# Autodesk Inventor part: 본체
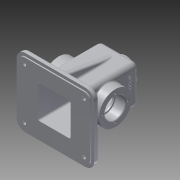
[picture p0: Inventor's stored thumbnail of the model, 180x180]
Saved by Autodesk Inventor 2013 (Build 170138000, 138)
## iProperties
Created: 2016-01
Part Number: 본체
Material: 알루미늄 6061
Document SubType Name: Modeling
Designer: User
Density: 2.71 g/cm^3
Mass: 806.269 g
Surface Area: 909.624 cm^2
Volume: 297.516 cm^3
Author: User
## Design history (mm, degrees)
sketch "스케치1"
  geometry: L1 (-32.5, 50)-(32.5, 50); L2 (32.5, 50)-(32.5, -50); L3 (32.5, -50)-(-32.5, -50); L4 (-32.5, -50)-(-32.5, 50); 3 further points
  constraints: 8 end point, 2 midpoint, 2 parallel, 1 horizontal, 1 horizontal alignment, 1 perpendicular, 1 vertical alignment
  dimensions: "d6" = 65 distance between parallel lines of L2 L4; "d8" = 100 distance between parallel lines of L3 L1
extrude "돌출1" new body sketch "스케치1" distance "d9" = 65; taper "d10" = 0 deg
sketch "스케치2"
  geometry: L1 (65, 0)-(65, 65) reference; L2 (0, 65)-(65, 65) reference; L3 (-32.5, 90)-(97.5, 90); L4 (97.5, 90)-(97.5, -25); L5 (97.5, -25)-(-32.5, -25); L6 (-32.5, -25)-(-32.5, 90); 5 further points
  constraints: 8 end point, 4 midpoint, 2 parallel, 1 horizontal, 1 horizontal alignment, 1 perpendicular, 1 vertical alignment
  dimensions: "d11" = 115 distance of L3.end L4.end; "d13" = 130 distance of L3.start L3.end
extrude "돌출2" join sketch "스케치2" distance "d14" = 10; taper "d15" = 0 deg
sketch "스케치3"
  geometry: L1 (97.5, 90)-(-32.5, 90) reference; L2 (97.5, -25)-(97.5, 90) reference; L3 (5, 60)-(60, 60); L4 (60, 60)-(60, 5); L5 (60, 5)-(5, 5); L6 (5, 5)-(5, 60); 5 further points
  constraints: 8 end point, 4 midpoint, 2 parallel, 1 horizontal, 1 horizontal alignment, 1 perpendicular, 1 vertical alignment
  dimensions: "d16" = 55 distance of L3.start L3.end; "d18" = 55 distance of L3.end L4.end
extrude "돌출3" cut sketch "스케치3" distance "d19" = 105; taper "d20" = 0 deg
sketch "스케치4"
  geometry: L1 (0, 0)-(65, 0) reference; L2 (90, -110)-(-25, -110) reference; C1 r 27.5 at (32.5, -55); 2 further points
  constraints: 1 centre point, 1 midpoint, 1 vertical alignment
  dimensions: "d21" = 55 diameter of C1; "d22" = 55 distance from line of C1.centre L2
extrude "돌출4" join sketch "스케치4" distance "d23" = 15; taper "d24" = 0 deg
sketch "스케치5"
  geometry: L1 (65, 0)-(0, 0) reference; L2 (90, -110)-(-25, -110) reference; C1 r 27.5 at (32.5, -55); 2 further points
  constraints: 1 centre point, 1 midpoint, 1 vertical alignment
  dimensions: "d25" = 55 diameter of C1; "d26" = 55 distance from line of C1.centre L2
extrude "돌출5" join sketch "스케치5" distance "d27" = 15; taper "d28" = 0 deg
sketch "스케치6"
  geometry: C1 r 27.5 at (0, 0) reference; C2 r 17.5 at (0, 0); C3 r 15 at (0, 0); 1 further point
  constraints: 2 centre point, 2 coincident
  dimensions: "d29" = 35 diameter of C2; "d30" = 30 diameter of C3
extrude "돌출6" cut sketch "스케치6" stored distance "d31" = 17; taper "d32" = 0 deg
extrude "돌출7" cut sketch "스케치6" distance "d33" = 17; taper "d34" = 0 deg
sketch "스케치7"
  geometry: C1 r 15 at (0, 0) reference; C2 r 27.5 at (0, 0) reference; C3 r 17.5 at (0, 0); 1 further point
  constraints: 1 centre point, 1 coincident
  dimensions: "d35" = 35 diameter of C3
extrude "돌출8" cut sketch "스케치7" distance "d36" = 17; taper "d37" = 0 deg
sketch "스케치8"
  geometry: L1 (0, 0)-(65, 0) reference; L2 (65, 0)-(65, -65) reference; C1 r 20 at (32.5, -32.5); 3 further points
  constraints: 2 midpoint, 1 centre point, 1 horizontal alignment, 1 vertical alignment
  dimensions: "d38" = 40 diameter of C1
extrude "돌출9" join sketch "스케치8" distance "d39" = 10; taper "d40" = 0 deg
sketch "스케치9"
  geometry: C1 r 20 at (0, 0) reference; C2 r 10.5 at (0, 0); 1 further point
  constraints: 1 centre point, 1 coincident
  dimensions: "d41" = 21 diameter of C2
extrude "돌출10" cut sketch "스케치9" distance "d42" = 46.75; taper "d43" = 0 deg
fillet "모깎기1" dims "d44" = 15
sketch "스케치10"
  geometry: C1 r 7.5 at (-17.5, 10); C2 r 7.5 at (82.5, 10); C3 r 7.5 at (82.5, -75); C4 r 7.5 at (-17.5, -75); C5 r 3 at (-17.5, 10); C6 r 3 at (82.5, 10); C7 r 3 at (82.5, -75); C8 r 3 at (-17.5, -75); A1 r 15 centre (-17.5, 10) between (-17.5, 25) and (-32.5, 10) reference; A2 r 15 centre (-17.5, -75) between (-32.5, -75) and (-17.5, -90) reference; A3 r 15 centre (82.5, -75) between (82.5, -90) and (97.5, -75) reference; A4 r 15 centre (82.5, 10) between (97.5, 10) and (82.5, 25) reference; 1 further point
  constraints: 8 centre point, 8 coincident
  dimensions: "d45" = 15 diameter of C1; "d46" = 15 diameter of C2; "d47" = 15 diameter of C3; "d48" = 15 diameter of C4; "d56" = 6 diameter of C5; "d57" = 6 diameter of C6; "d58" = 6 diameter of C7; "d59" = 6 diameter of C8
extrude "돌출11" cut sketch "스케치10" stored distance "d60" = 15 (= d47); taper "d61" = 0 deg
extrude "돌출12" join sketch "스케치10" distance "d62" = 3; taper "d63" = 0 deg
sketch "스케치11"
  geometry: L1 (-17.5, -25)-(82.5, -25) reference; L2 (97.5, -10)-(97.5, 75) reference; L3 (82.5, 90)-(-17.5, 90) reference; L4 (-32.5, 75)-(-32.5, -10) reference; L5 (-27.5, 85)-(92.5, 85); L6 (92.5, 85)-(92.5, -20); L7 (-27.5, -20)-(-27.5, 85); L8 (5, 5)-(5, 60) reference; L9 (5, 60)-(60, 60) reference; L10 (60, 5)-(5, 5) reference; L11 (92.5, -20)-(-27.5, -20); A1 r 15 centre (-17.5, -10) between (-32.5, -10) and (-17.5, -25) reference; A2 r 15 centre (82.5, -10) between (82.5, -25) and (97.5, -10) reference; A3 r 15 centre (82.5, 75) between (97.5, 75) and (82.5, 90) reference; A4 r 15 centre (-17.5, 75) between (-17.5, 90) and (-32.5, 75) reference; 7 further points
  constraints: 8 end point, 6 midpoint, 2 parallel, 2 vertical alignment, 1 horizontal alignment
  dimensions: "d64" = 5 distance between parallel lines of L2 L6; "d115" = 105 distance between parallel lines of L11 L5
extrude "돌출13" cut sketch "스케치11" distance "d65" = 2; taper "d66" = 0 deg
node "작업 평면2"
sketch "스케치12"
  geometry: L1 (-25, -100)-(-10, -100) reference; L2 (-17.5, -100)-(-2.5, -100) reference; L3 (75, -100)-(-10, -100) reference; L4 (0, 0)-(0, -100) reference; L5 (75, -100)-(90, -100) reference; L6 (65, -100)-(65, 0) reference; L7 (-15, -100)-(0, -14.931); L8 (80, -100)-(65, -14.931); 1 further point
  constraints: 4 end point, 4 point on line
  dimensions: "d67" = 10 distance of L7.start L1.start; "d68" = 10 distance of L8.start L5.end; "d71" = 10 deg angle of L6 L8; "d72" = 10 deg angle of L4 L7
feature "리브1" dims "d73" = 1, "d74" = 10, "d75" = 0, "d76" = 0, "d77" = 1, "d78" = 1
feature "리브2" dims "d79" = 1, "d80" = 10, "d81" = 0, "d82" = 0, "d83" = 1, "d84" = 1
sketch "스케치13" dims "d85" = 42
  geometry: C1 r 27.5 at (0, 0) reference; 3 further points
  constraints: 2 vertical alignment, 1 coincident, 2 other
hole "구멍2" sketch "스케치13" at (0, 21) diameter "d86" = 3.242; stored, may be unused: countersink angle "d90" = 90 deg, drill point angle "d92" = 118 deg; dims "d87" = 8, "d88" = 4, "d89" = 2, "d91" = 10
sketch "스케치14" dims "d96" = 29
  geometry: C1 r 10.5 at (0, 0) reference; 3 further points
  constraints: 2 vertical alignment, 1 coincident, 2 other
hole "구멍3" sketch "스케치14" at (0, 14.5) diameter "d97" = 2.459; stored, may be unused: countersink angle "d101" = 90 deg, drill point angle "d103" = 118 deg; dims "d98" = 7, "d99" = 4, "d100" = 2, "d102" = 9
fillet "모깎기2" dims "d107" = 0.3
fillet "모깎기3" dims "d108" = 0.3
chamfer "모따기1" distance "d109" = 1; stored, may be unused: second distance "d110" = 2, angle "d111" = 45 deg
chamfer "모따기2" distance "d112" = 1; stored, may be unused: second distance "d113" = 2, angle "d114" = 45 deg
fillet "모깎기4" dims "d116" = 10
node "작업 평면3"
sketch "스케치15"
  geometry: L1 (50, -50)-(-50, -50) reference; L2 (-32.5, -50)-(-32.5, 50) reference; L3 (-32.5, -32.5)-(-47.5, -32.5) reference; L4 (32.5, 50)-(32.5, -50) reference; L5 (32.5, -32.5)-(47.5, -32.5) reference; L6 (42.5, -32.5)-(42.5, -50); L7 (-42.5, -32.5)-(-42.5, -50); L8 (-27.5, -60)-(-27.5, 45) reference; L9 (27.5, -60)-(27.5, 45) reference; 1 further point
  constraints: 4 end point, 4 point on line, 1 parallel, 1 vertical
  dimensions: "d117" = 15 distance between parallel lines of L7 L8; "d118" = 15 distance between parallel lines of L6 L9
feature "리브3" dims "d119" = 1, "d120" = 6, "d121" = 0, "d122" = 0, "d123" = 1, "d124" = 1
feature "리브4" dims "d125" = 1, "d126" = 6, "d127" = 0, "d128" = 0, "d129" = 1, "d130" = 1
fillet "모깎기5" dims "d131" = 8
fillet "모깎기6" dims "d132" = 8
fillet "모깎기7" dims "d133" = 3
fillet "모깎기8" dims "d134" = 3
fillet "모깎기9" dims "d135" = 1
fillet "모깎기10" dims "d136" = 3
fillet "모깎기12" dims "d138" = 3
sketch "스케치16"
  geometry: L1 (-8, 0)-(-8, -91) reference; L2 (44.5, 18)-(4.5, 18) reference; 2 further points
  constraints: 1 other
  dimensions: "d139" = 32.5 distance from line of point (24.5, -8) L1; "d140" = 26 distance from line of point (24.5, -8) L2
feature "엠보싱1" sketch "스케치16" dims "d141" = 0.5, "d142" = 0
feature "면 기울기1" dims angle "d143" = 5 deg
fillet "모깎기13" dims "d144" = 3
fillet "모깎기14" dims "d145" = 3
node "솔리드1"
pattern_circular "원형 패턴1" dims angle "d94" = 360 deg
mirror "대칭1"
pattern_circular "원형 패턴2" dims angle "d105" = 360 deg
